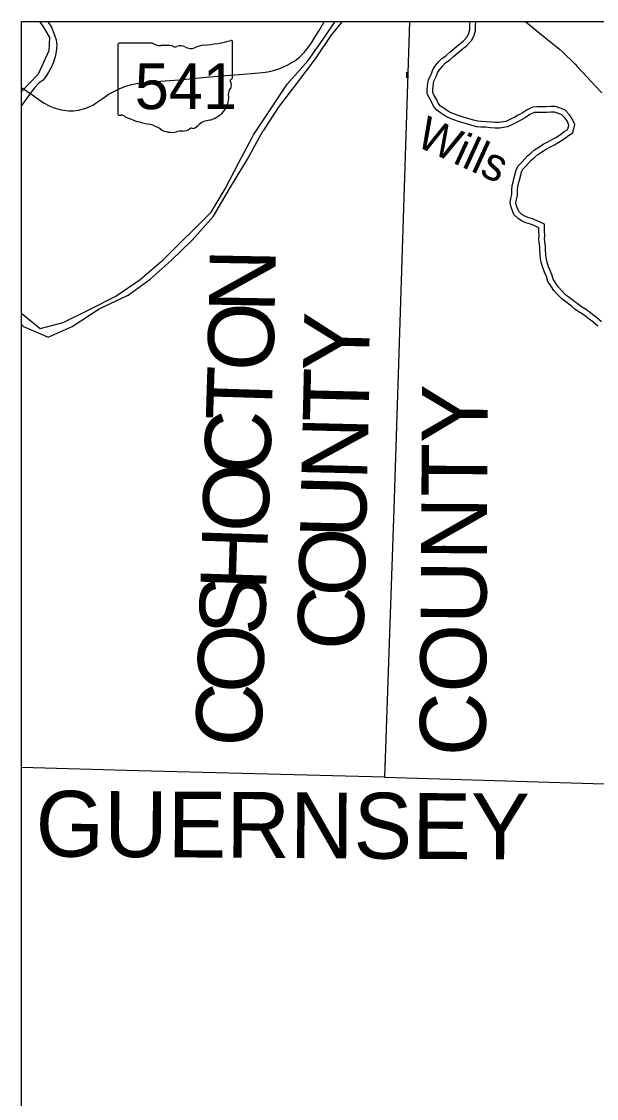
# Model space of a CAD drawing. Extents: x -12.1 to 34, y 0 to 22.
# Drawn here: x -12.146 to -10.595, y 17.402 to 20.306 of the extents above; entities that cross this region are included whole.
import ezdxf

# ---------------------------------------------------------------- set-up
doc = ezdxf.new("R2010")
doc.units = 0
for name, color, linetype in [('GM_X_County', 7, 'Continuous'), ('GM_X_County_Text', 7, 'Continuous'), ('GM_X_Major_River', 7, 'Continuous'), ('GM_X_Major_River_Text', 7, 'Continuous'), ('GM_X_Minor_Lake', 7, 'Continuous'), ('GM_X_Minor_River', 7, 'Continuous'), ('GM_X_State_Route', 7, 'Continuous'), ('GM_X_State_Shield', 7, 'Continuous'), ('GM_X_Township', 7, 'Continuous'), ('SH_Text', 7, 'Continuous')]:
    doc.layers.add(name, color=color, linetype=linetype)

msp = doc.modelspace()

# ---------------------------------------------------------------- linework, layer by layer
at = {"layer": 'GM_X_County'}
msp.add_lwpolyline([(-11.1, 20.3063), (-11.1424, 18.9924), (-11.1671, 18.2681), (-11.8317, 18.2855), (-12.1463, 18.2946)], dxfattribs=at)
at = {"layer": 'GM_X_Major_River'}
for points in [[(-12.0982, 20.3063), (-12.0867, 20.2913), (-12.0713, 20.2628), (-12.073, 20.227), (-12.1014, 20.1644), (-12.1463, 20.1176)], [(-12.1463, 19.4889), (-12.1414, 19.484), (-12.0743, 19.4555), (-12.0093, 19.4842), (-11.9367, 19.5312), (-11.8589, 19.568), (-11.7991, 19.6116), (-11.7428, 19.6616), (-11.6858, 19.7169), (-11.6283, 19.7814), (-11.585, 19.8549), (-11.5366, 19.9355), (-11.4954, 20.0104), (-11.4918, 20.0143), (-11.4535, 20.074), (-11.4039, 20.1392), (-11.3531, 20.2059), (-11.3113, 20.2687), (-11.2807, 20.3063)], [(-12.1463, 19.5191), (-12.1443, 19.5178), (-12.0957, 19.478), (-12.0337, 19.4946), (-11.963, 19.5293), (-11.8919, 19.5654), (-11.8261, 19.6103), (-11.763, 19.6645), (-11.635, 19.7925), (-11.5974, 19.8547), (-11.5601, 19.9261), (-11.5235, 19.995), (-11.5203, 20.0007), (-11.4752, 20.0677), (-11.4297, 20.1373), (-11.3734, 20.2014), (-11.3265, 20.2681), (-11.2999, 20.3063)], [(-12.0756, 20.3063), (-12.0753, 20.3057), (-12.0651, 20.2915), (-12.0571, 20.2698), (-12.0529, 20.2573), (-12.0512, 20.2438), (-12.0517, 20.2325), (-12.0535, 20.2205), (-12.0561, 20.2088), (-12.0601, 20.1964), (-12.0665, 20.1826), (-12.0737, 20.1699), (-12.0787, 20.1603), (-12.0884, 20.148), (-12.0987, 20.1406)], [(-10.9908, 20.2236), (-10.9795, 20.2333), (-10.9679, 20.243), (-10.9553, 20.253), (-10.9444, 20.2649), (-10.9399, 20.2748), (-10.9371, 20.2844), (-10.9366, 20.2965), (-10.9358, 20.3063)], [(-10.9808, 20.2121), (-10.9696, 20.2217), (-10.9583, 20.2312), (-10.9448, 20.2419), (-10.9315, 20.2564), (-10.9255, 20.2696), (-10.922, 20.2819), (-10.9213, 20.2956), (-10.9206, 20.3063)], [(-10.9807, 20.2122), (-10.9696, 20.2217), (-10.9583, 20.2312), (-10.9448, 20.2419), (-10.9315, 20.2564), (-10.9255, 20.2696), (-10.922, 20.2819), (-10.9213, 20.2956), (-10.9206, 20.3063)], [(-10.6052, 19.4967), (-10.6149, 19.504), (-10.6242, 19.5107), (-10.6338, 19.5177), (-10.6445, 19.5243), (-10.6534, 19.531), (-10.6627, 19.5387), (-10.6784, 19.5503), (-10.6887, 19.5583), (-10.6995, 19.5696), (-10.7102, 19.5805), (-10.7167, 19.5907), (-10.7264, 19.6051), (-10.7301, 19.6186), (-10.7355, 19.6306), (-10.7395, 19.6398), (-10.7432, 19.6536), (-10.7461, 19.6663), (-10.7473, 19.6773), (-10.7478, 19.6897), (-10.7482, 19.699), (-10.7497, 19.7103), (-10.7505, 19.7192), (-10.7499, 19.7302), (-10.7507, 19.7405), (-10.7508, 19.75), (-10.7612, 19.7549), (-10.7729, 19.7597), (-10.7857, 19.7635), (-10.7957, 19.768), (-10.806, 19.774), (-10.8182, 19.7859), (-10.8254, 19.8053), (-10.828, 19.8174), (-10.826, 19.8288), (-10.8236, 19.8401), (-10.8234, 19.8511), (-10.8228, 19.8643), (-10.8201, 19.8732), (-10.818, 19.882), (-10.8143, 19.8956), (-10.8122, 19.9055), (-10.8063, 19.9173), (-10.7965, 19.927), (-10.7811, 19.9438), (-10.772, 19.9517), (-10.7625, 19.9599), (-10.7508, 19.9671), (-10.7392, 19.9754), (-10.7262, 19.9819), (-10.7163, 19.9873), (-10.7047, 19.9938), (-10.692, 20.0014), (-10.6825, 20.0093), (-10.6727, 20.0154), (-10.6696, 20.0272), (-10.6739, 20.0364), (-10.6797, 20.0455), (-10.689, 20.055), (-10.6982, 20.0581), (-10.7086, 20.0619), (-10.7181, 20.0622), (-10.7295, 20.0613), (-10.7422, 20.0612), (-10.7546, 20.0611), (-10.7638, 20.0606), (-10.7747, 20.0552), (-10.7846, 20.0484), (-10.799, 20.0401), (-10.8093, 20.035), (-10.8205, 20.0296), (-10.8354, 20.0223), (-10.8573, 20.0186), (-10.869, 20.0185), (-10.8814, 20.0194), (-10.8938, 20.021), (-10.9073, 20.0216), (-10.9183, 20.0226), (-10.9314, 20.026), (-10.9428, 20.0294), (-10.9527, 20.0322), (-10.9673, 20.037), (-10.9776, 20.0401), (-10.9918, 20.0456), (-11.0025, 20.0508), (-11.0157, 20.0599), (-11.0264, 20.0669), (-11.0354, 20.0781), (-11.0394, 20.088), (-11.0462, 20.1), (-11.052, 20.1117), (-11.0521, 20.1212), (-11.0508, 20.134), (-11.0488, 20.15), (-11.0408, 20.1653), (-11.0381, 20.1742), (-11.0311, 20.1853), (-11.0213, 20.1974), (-11.0122, 20.2064), (-11.0006, 20.215), (-10.9908, 20.2236)], [(-10.596, 19.5088), (-10.6058, 19.5163), (-10.6152, 19.523), (-10.6253, 19.5303), (-10.6359, 19.5369), (-10.644, 19.5429), (-10.6533, 19.5507), (-10.6692, 19.5624), (-10.6785, 19.5696), (-10.6885, 19.5802), (-10.6982, 19.59), (-10.7039, 19.599), (-10.7123, 19.6115), (-10.7157, 19.6238), (-10.7216, 19.6368), (-10.7251, 19.6448), (-10.7284, 19.6573), (-10.7311, 19.6689), (-10.7321, 19.6784), (-10.7325, 19.6904), (-10.733, 19.7003), (-10.7346, 19.712), (-10.7353, 19.7194), (-10.7347, 19.7304), (-10.7355, 19.7411), (-10.7357, 19.7597), (-10.755, 19.7688), (-10.7678, 19.7741), (-10.7804, 19.7778), (-10.7887, 19.7816), (-10.7967, 19.7862), (-10.8051, 19.7944), (-10.8108, 19.8096), (-10.8125, 19.8177), (-10.811, 19.8259), (-10.8084, 19.8384), (-10.8082, 19.8506), (-10.8077, 19.8616), (-10.8053, 19.8692), (-10.8033, 19.8783), (-10.7994, 19.892), (-10.7977, 19.9005), (-10.7938, 19.9082), (-10.7855, 19.9164), (-10.7704, 19.9329), (-10.762, 19.9402), (-10.7534, 19.9477), (-10.7424, 19.9545), (-10.7313, 19.9623), (-10.7191, 19.9685), (-10.7089, 19.974), (-10.6971, 19.9807), (-10.6832, 19.989), (-10.6736, 19.997), (-10.6595, 20.0057), (-10.6534, 20.0287), (-10.6605, 20.0437), (-10.6677, 20.055), (-10.6807, 20.0683), (-10.6932, 20.0725), (-10.7056, 20.077), (-10.7185, 20.0774), (-10.7301, 20.0765), (-10.7424, 20.0764), (-10.755, 20.0763), (-10.7677, 20.0757), (-10.7825, 20.0683), (-10.7928, 20.0612), (-10.8062, 20.0535), (-10.816, 20.0487), (-10.8272, 20.0433), (-10.8401, 20.037), (-10.8587, 20.0338), (-10.8685, 20.0337), (-10.8798, 20.0345), (-10.8925, 20.0362), (-10.9063, 20.0368), (-10.9157, 20.0376), (-10.9273, 20.0406), (-10.9385, 20.044), (-10.9483, 20.0467), (-10.9627, 20.0515), (-10.9726, 20.0545), (-10.9857, 20.0595), (-10.9948, 20.064), (-11.0072, 20.0725), (-11.016, 20.0783), (-11.0221, 20.0859), (-11.0256, 20.0947), (-11.0328, 20.1072), (-11.0368, 20.1153), (-11.0368, 20.1206), (-11.0357, 20.1323), (-11.034, 20.1454), (-11.0267, 20.1595), (-11.0241, 20.1678), (-11.0187, 20.1764), (-11.01, 20.1872), (-11.0022, 20.1948), (-10.991, 20.2032), (-10.9807, 20.2122)], [(-10.5955, 19.5084), (-10.6058, 19.5163), (-10.6152, 19.523), (-10.6253, 19.5303), (-10.6359, 19.5369), (-10.644, 19.5429), (-10.6533, 19.5507), (-10.6692, 19.5624), (-10.6785, 19.5696), (-10.6885, 19.5802), (-10.6982, 19.59), (-10.7039, 19.599), (-10.7123, 19.6115), (-10.7157, 19.6238), (-10.7216, 19.6368), (-10.7251, 19.6448), (-10.7284, 19.6573), (-10.7311, 19.6689), (-10.7321, 19.6784), (-10.7325, 19.6904), (-10.733, 19.7003), (-10.7346, 19.712), (-10.7353, 19.7194), (-10.7347, 19.7304), (-10.7355, 19.7411), (-10.7357, 19.7597), (-10.755, 19.7688), (-10.7678, 19.7741), (-10.7804, 19.7778), (-10.7887, 19.7816), (-10.7967, 19.7862), (-10.8051, 19.7944), (-10.8108, 19.8096), (-10.8125, 19.8177), (-10.811, 19.8259), (-10.8084, 19.8384), (-10.8082, 19.8506), (-10.8077, 19.8616), (-10.8053, 19.8692), (-10.8033, 19.8783), (-10.7994, 19.892), (-10.7977, 19.9005), (-10.7938, 19.9082), (-10.7855, 19.9164), (-10.7704, 19.9329), (-10.762, 19.9402), (-10.7534, 19.9477), (-10.7424, 19.9545), (-10.7313, 19.9623), (-10.7191, 19.9685), (-10.7089, 19.974), (-10.6971, 19.9807), (-10.6832, 19.989), (-10.6736, 19.997), (-10.6595, 20.0057), (-10.6534, 20.0287), (-10.6605, 20.0437), (-10.6677, 20.055), (-10.6807, 20.0683), (-10.6932, 20.0725), (-10.7056, 20.077), (-10.7185, 20.0774), (-10.7301, 20.0765), (-10.7424, 20.0764), (-10.755, 20.0763), (-10.7677, 20.0757), (-10.7825, 20.0683), (-10.7928, 20.0612), (-10.8062, 20.0535), (-10.816, 20.0487), (-10.8272, 20.0433), (-10.8401, 20.037), (-10.8587, 20.0338), (-10.8685, 20.0337), (-10.8798, 20.0345), (-10.8925, 20.0362), (-10.9063, 20.0368), (-10.9157, 20.0376), (-10.9273, 20.0406), (-10.9385, 20.044), (-10.9483, 20.0467), (-10.9627, 20.0515), (-10.9726, 20.0545), (-10.9857, 20.0595), (-10.9948, 20.064), (-11.0072, 20.0725), (-11.016, 20.0783), (-11.0221, 20.0859), (-11.0256, 20.0947), (-11.0328, 20.1072), (-11.0368, 20.1153), (-11.0368, 20.1206), (-11.0357, 20.1323), (-11.034, 20.1454), (-11.0267, 20.1595), (-11.0241, 20.1678), (-11.0187, 20.1764), (-11.01, 20.1872), (-11.0022, 20.1948), (-10.991, 20.2032), (-10.9807, 20.2122)], [(-12.0987, 20.1406), (-12.1119, 20.1269), (-12.1463, 20.0801)], [(-10.5917, 19.4847), (-10.6052, 19.4967)], [(-10.582, 19.4965), (-10.5955, 19.5084)]]:
    msp.add_lwpolyline(points, dxfattribs=at)
at = {"layer": 'GM_X_Minor_Lake'}
msp.add_line((-11.107, 20.1541), (-11.1065, 20.1695), dxfattribs=at)
at = {"layer": 'GM_X_Minor_River'}
msp.add_lwpolyline([(-11.1651, 18.3051), (-11.165, 18.3044)], dxfattribs=at)
at = {"layer": 'GM_X_State_Route'}
for points in [[(-12.1463, 20.128), (-12.1162, 20.1074), (-12.1019, 20.0975), (-12.0855, 20.0861), (-12.072, 20.0787), (-12.0581, 20.0731), (-12.0465, 20.0696), (-12.0333, 20.0669), (-12.0187, 20.0657), (-12.0059, 20.0657), (-11.9927, 20.0673), (-11.9756, 20.0717), (-11.9641, 20.0761), (-11.9525, 20.082), (-11.9454, 20.0867), (-11.9265, 20.1), (-11.91, 20.1111), (-11.8958, 20.1187), (-11.8807, 20.1261), (-11.8652, 20.1321), (-11.8488, 20.1366), (-11.8365, 20.1388), (-11.8246, 20.1406), (-11.7717, 20.1451), (-11.7208, 20.1492), (-11.6576, 20.1553), (-11.608, 20.1596), (-11.5479, 20.1641), (-11.4959, 20.1687), (-11.4816, 20.1706), (-11.4706, 20.1733), (-11.4495, 20.1796), (-11.4298, 20.1884), (-11.4088, 20.2), (-11.3963, 20.2101), (-11.3842, 20.2225), (-11.3729, 20.2359), (-11.3638, 20.2489), (-11.3557, 20.262), (-11.3438, 20.2821), (-11.3298, 20.3055), (-11.3293, 20.3063)], [(-10.7867, 20.3063), (-10.7552, 20.2807), (-10.7129, 20.2461), (-10.6953, 20.2316), (-10.6869, 20.2244), (-10.6741, 20.2124), (-10.6654, 20.2039), (-10.6572, 20.1956), (-10.6528, 20.191), (-10.6464, 20.1843), (-10.5978, 20.1324), (-10.5805, 20.1142)]]:
    msp.add_lwpolyline(points, dxfattribs=at)
at = {"layer": 'GM_X_State_Shield'}
for p, q in [((-11.8864, 20.2444), (-11.8864, 20.0568)), ((-11.7928, 20.2476), (-11.8833, 20.2476)), ((-11.5774, 20.1541), (-11.5774, 20.2523)), ((-11.5774, 20.1542), (-11.5774, 20.1541))]:
    msp.add_line(p, q, dxfattribs=at)
for centre, major_axis, start_param, end_param in [((-11.8828, 20.2448), (0.00358, 0), 1.712693, 3.28349), ((-11.7713, 20.2694), (0.0347, 0), 4.042523, 4.731795), ((-11.6874, 20.5034), (0.3277, 0), 4.814394, 5.042369), ((-11.5808, 20.2527), (0.00344, 0), 6.141152, 7.989035), ((-11.7598, 20.1423), (0.1246, 0), 1.404758, 1.657858), ((-11.7315, 20.2458), (0.01, 0), 3.836095, 5.185415), ((-11.7168, 20.2241), (0.0208, 0), 0.950623, 2.079405), ((-11.6899, 20.2538), (0.0251, 0), 4.081561, 5.145723), ((-11.6456, 20.1903), (0.0659, 0), 1.699011, 2.107814), ((-11.5782, 20.1469), (0.00532, 0), 1.883978, 3.671073), ((-11.612, 20.1345), (0.032, 0), 5.934695, 6.695948), ((-11.581, 20.1538), (0.00368, 0), 5.05454, 6.418171), ((-11.6691, 20.1006), (0.082, 0), 5.101752, 6.440018), ((-11.565, 20.1131), (0.0232, 0), 2.387724, 3.262537), ((-11.8828, 20.0564), (0.00361, 0), 3.00124, 4.508301), ((-11.8822, 20.0756), (0.0276, 0), 4.665946, 4.897461), ((-11.8766, 20.046), (0.00994, 0), 0.519207, 1.627899), ((-11.7511, 20.2145), (0.2366, 0), 4.195997, 4.488961), ((-11.6345, 20.0041), (0.0449, 0), 1.647645, 2.488434), ((-11.8217, 19.9725), (0.074, 0), 0.823519, 1.323587), ((-11.7416, 20.045), (0.047, 0), 4.026481, 4.996735), ((-11.7145, 19.9802), (0.0386, 0), 1.495662, 1.94098), ((-11.711, 20.031), (0.025, 0), 4.691044, 5.507374), ((-11.6884, 20.0128), (0.00705, 0), 1.147584, 2.315152), ((-11.6914, 20.0386), (0.0265, 0), 4.937069, 5.64225)]:
    msp.add_ellipse(centre, major_axis=major_axis, ratio=0.8, start_param=start_param, end_param=end_param, dxfattribs=at)
at = {"layer": 'GM_X_Township'}
msp.add_lwpolyline([(-11.1671, 18.2681), (-10.4859, 18.2476)], dxfattribs=at)
at = {"layer": 'SH_Text'}
msp.add_lwpolyline([(-12.1463, 20.3063), (-4.4383, 20.3063), (-4.4383, 10.9773), (-12.1463, 10.9773)], close=True, dxfattribs=at)

# ---------------------------------------------------------------- texts
at = {"layer": 'GM_X_County_Text'}
for s, height, rotation, p in [('N', 0.1776, 88.9622, (-11.4635, 19.5202)), ('O', 0.1776, 88.469, (-11.4677, 19.3619)), ('Y', 0.1776, 88.6358, (-11.2096, 19.3618)), ('T', 0.1776, 88.2126, (-11.4718, 19.2285)), ('T', 0.1776, 88.6358, (-11.2104, 19.2243)), ('COUNTY', 0.17756, 89.6417, (-10.8945, 18.3248)), ('C', 0.1776, 88.1616, (-11.4765, 19.0837)), ('N', 0.1776, 88.6373, (-11.2141, 19.0676)), ('O', 0.1776, 88.1583, (-11.4815, 18.927)), ('U', 0.1776, 88.6368, (-11.2178, 18.911)), ('H', 0.1776, 88.1594, (-11.4866, 18.7704)), ('O', 0.1776, 88.6499, (-11.2215, 18.7543)), ('S', 0.1776, 88.159, (-11.4904, 18.6497)), ('C', 0.1776, 88.7376, (-11.2247, 18.6097)), ('O', 0.1776, 88.1594, (-11.4955, 18.4931)), ('C', 0.1776, 88.1594, (-11.5001, 18.3484)), ('GUERNSEY', 0.17756, 359.6417, (-12.1087, 18.0545))]:
    msp.add_text(s, height=height, rotation=rotation, dxfattribs=at).set_placement(p)
at = {"layer": 'GM_X_Major_River_Text'}
msp.add_text('Wills', height=0.08874, rotation=335.4321, dxfattribs=at).set_placement((-11.0871, 19.9728))
at = {"layer": 'GM_X_State_Shield'}
msp.add_text('541', height=0.1236, dxfattribs=at).set_placement((-11.8408, 20.07))

doc.saveas('drawing.dxf')
